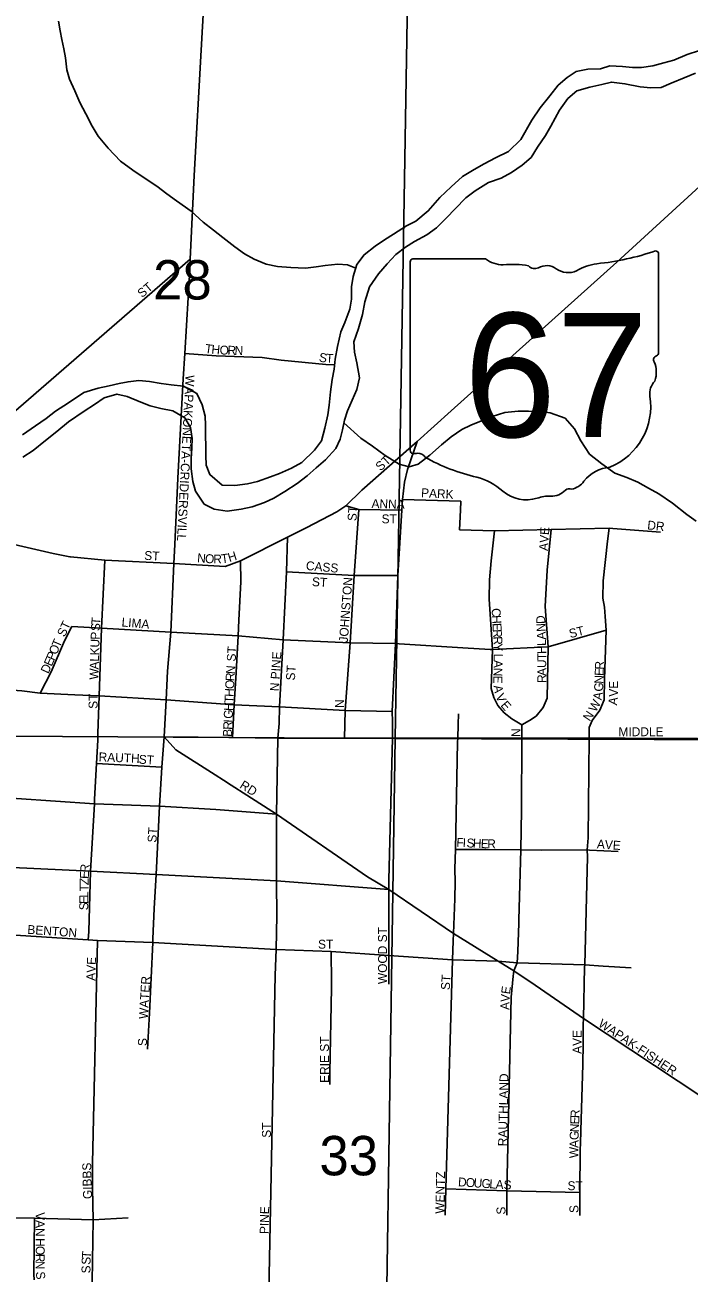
# Model space of a CAD drawing. Extents: x -784 to 1375, y -225 to 440.
# Drawn here: x 105.2 to 133.1, y 334.5 to 387.1 of the extents above; entities that cross this region are included whole.
import ezdxf

# ---------------------------------------------------------------- set-up
doc = ezdxf.new("R2010")
doc.units = 0
for name, color, linetype in [('GM_X_City_Street', 7, 'Continuous'), ('GM_X_City_Street_Text', 7, 'Continuous'), ('GM_X_Major_River', 7, 'Continuous'), ('GM_X_Minor_River', 7, 'Continuous'), ('GM_X_Section', 7, 'Continuous'), ('GM_X_Section_Text', 7, 'Continuous'), ('GM_X_State_Location', 7, 'Continuous'), ('GM_X_State_Route', 7, 'Continuous'), ('GM_X_State_Shield', 7, 'Continuous')]:
    doc.layers.add(name, color=color, linetype=linetype)

msp = doc.modelspace()

# ---------------------------------------------------------------- linework, layer by layer
at = {"layer": 'GM_X_City_Street'}
for points in [[(112.107, 376.784), (112.133, 377.221), (112.296, 380.735), (112.591, 386.006), (112.762, 389.014)], [(107.019, 372.788), (112.133, 377.221)], [(111.475, 365.212), (111.602, 368.004), (111.831, 372.18), (111.896, 373.25), (112.107, 376.784)], [(111.896, 373.25), (113.22, 373.152), (115.156, 373.078), (115.949, 372.972), (117.836, 372.788), (118.217, 372.764)], [(91.136, 368.057), (92.218, 368.088), (95.074, 368.197), (97.931, 368.286), (100.615, 368.4), (101.44, 368.441), (103.41, 369.658), (107.019, 372.788)], [(111.438, 364.408), (111.438, 364.408), (113.596, 364.282), (114.241, 364.525), (116.222, 365.515), (117.027, 365.93), (118.298, 366.578), (118.675, 366.84), (119.346, 367.498), (121.677, 369.543)], [(118.643, 358.22), (118.86, 361.075), (119.022, 363.909), (119.215, 366.68)], [(118.675, 366.84), (119.215, 366.68), (121.032, 366.649)], [(121.064, 367.096), (123.511, 367.026), (123.494, 366.648)], [(123.494, 366.648), (123.46, 365.831), (124.927, 365.786), (127.311, 365.838), (129.746, 365.895), (129.903, 365.882)], [(126.072, 357.619), (125.651, 357.865), (125.338, 358.13), (125.066, 358.431), (124.9, 358.772), (124.792, 359.143), (124.839, 360.787), (124.705, 362.905), (124.724, 363.723), (124.795, 364.522), (124.927, 365.786)], [(126.085, 357.057), (126.072, 357.619), (126.401, 357.808), (126.679, 357.983), (126.982, 358.347), (127.142, 358.737), (127.187, 360.905), (127.063, 362.593), (127.139, 364.125), (127.311, 365.838)], [(128.918, 357.068), (128.918, 357.501), (129.033, 357.801), (129.356, 358.242), (129.541, 358.676), (129.56, 359.545), (129.626, 361.602), (129.584, 362.184), (129.556, 362.578), (129.483, 362.944), (129.503, 363.685), (129.68, 365.342), (129.746, 365.895)], [(129.903, 365.882), (131.915, 365.724)], [(103.944, 365.378), (103.973, 365.372), (106.368, 364.833), (107.061, 364.692)], [(111.111, 358.673), (111.169, 359.874), (111.309, 361.516), (111.438, 364.408), (111.475, 365.212)], [(115.883, 358.373), (116.044, 361.202), (116.184, 364.065), (116.222, 365.515)], [(107.061, 364.692), (107.087, 364.686), (108.542, 364.551), (111.438, 364.408)], [(108.294, 358.836), (108.396, 361.682), (108.542, 364.551)], [(114.06, 359.824), (114.152, 361.369), (114.171, 362.027), (114.254, 363.643), (114.241, 364.525)], [(116.184, 364.065), (119.022, 363.909), (120.859, 363.897)], [(105.812, 358.954), (106.278, 359.844), (106.842, 361.152), (107.144, 361.757)], [(107.144, 361.757), (108.396, 361.682), (111.309, 361.516), (114.152, 361.369), (116.044, 361.202), (118.86, 361.075), (120.77, 361.037), (120.92, 361.028)], [(124.745, 360.793), (124.839, 360.787), (127.187, 360.905), (129.626, 361.602)], [(120.92, 361.028), (123.597, 360.863)], [(123.597, 360.863), (124.745, 360.793)], [(113.903, 357.083), (113.98, 358.462), (114.06, 359.824)], [(99.332, 359.444), (102.266, 359.248), (105.044, 359.044), (105.812, 358.954), (107.272, 358.878), (108.266, 358.837)], [(108.245, 357.255), (108.294, 358.836)], [(108.266, 358.837), (108.294, 358.836), (111.111, 358.673)], [(111.035, 357.115), (111.111, 358.673)], [(111.111, 358.673), (113.98, 358.462), (115.883, 358.373), (118.643, 358.22), (120.63, 358.181)], [(115.758, 353.703), (115.757, 353.865), (115.813, 357.063), (115.864, 357.67), (115.883, 358.373)], [(118.617, 357.063), (118.643, 358.22)], [(123.379, 356.885), (123.383, 357.063), (123.402, 357.632), (123.415, 358.079)], [(108.106, 354.49), (108.186, 355.987), (108.237, 356.98), (108.245, 357.255)], [(110.561, 348.607), (110.607, 349.893), (110.696, 351.324), (110.837, 354.198), (110.932, 355.834), (111.035, 357.115)], [(111.035, 357.115), (113.903, 357.083), (115.813, 357.063), (118.617, 357.063), (120.642, 357.063), (121.997, 357.057), (123.383, 357.063), (125.938, 357.057)], [(120.48, 350.682), (119.591, 351.217), (115.757, 353.865), (114.506, 354.664), (113.845, 355.086), (113.527, 355.289), (113.183, 355.509), (111.53, 356.565), (111.035, 357.115)], [(123.194, 348.525), (123.209, 348.835), (123.254, 350.292), (123.268, 351.013), (123.259, 351.561), (123.287, 352.374), (123.379, 356.885)], [(125.938, 357.057), (126.085, 357.057), (128.918, 357.068), (130.422, 357.063), (133.463, 357.044), (138.325, 357.009), (140.841, 356.958)], [(125.951, 349.415), (126.04, 352.355), (126.063, 354.029), (126.085, 357.057)], [(128.72, 347.422), (128.722, 347.515), (128.84, 352.068), (128.829, 352.355), (128.863, 352.862), (128.918, 357.068)], [(80.071, 355.87), (83.086, 355.68), (86.015, 355.53), (88.849, 355.346), (91.692, 355.228), (94.544, 355.08), (96.031, 354.974), (97.444, 354.917), (98.204, 354.868), (99.079, 354.811), (101.947, 354.664), (104.821, 354.525), (108.096, 354.301), (110.837, 354.198), (113.207, 354.051), (115.757, 353.865)], [(108.186, 355.987), (110.932, 355.834)], [(107.839, 348.564), (107.859, 348.922), (107.93, 351.458), (108.096, 354.301), (108.106, 354.49)], [(115.762, 350.978), (115.762, 351.055), (115.758, 353.703)], [(123.287, 352.374), (124.565, 352.368), (126.04, 352.355), (126.896, 352.349), (128.829, 352.355), (128.925, 352.351)], [(128.925, 352.351), (130.132, 352.295)], [(115.42, 333.071), (115.698, 347.082), (115.743, 348.168), (115.768, 349.599), (115.762, 350.978)], [(120.479, 347.901), (120.479, 347.915), (120.479, 347.964), (120.48, 350.473), (120.48, 350.682)], [(120.48, 350.682), (123.209, 348.835), (125.081, 347.668), (125.739, 347.264), (126.389, 346.827), (126.452, 346.784)], [(125.717, 347.035), (125.739, 347.264), (125.889, 347.601), (125.905, 348.081), (125.947, 349.276), (125.951, 349.415)], [(98.761, 349.05), (101.574, 348.935), (103.26, 348.845), (104.551, 348.781), (107.839, 348.564), (108.231, 348.541), (110.555, 348.456), (115.743, 348.168), (118.054, 348.079), (120.479, 347.915), (123.155, 347.733), (125.081, 347.668), (125.889, 347.601), (128.722, 347.515), (129.501, 347.466)], [(108.016, 339.136), (108.016, 339.167), (108.231, 348.541)], [(110.338, 343.965), (110.421, 345.479), (110.555, 348.456), (110.561, 348.607)], [(122.849, 336.983), (122.881, 338.086), (123.155, 347.733), (123.194, 348.525)], [(118.07, 346.788), (118.054, 348.079)], [(120.479, 346.709), (120.479, 347.127), (120.479, 347.901)], [(128.665, 345.01), (128.669, 345.259), (128.72, 347.422)], [(129.501, 347.466), (130.683, 347.392)], [(117.996, 342.483), (117.996, 342.986), (118.073, 346.549), (118.07, 346.788)], [(125.445, 336.983), (125.454, 338.009), (125.633, 346.153), (125.717, 347.035)], [(126.452, 346.784), (128.669, 345.259), (142.616, 336.025)], [(128.513, 336.971), (128.517, 337.368), (128.522, 337.941), (128.539, 339.753), (128.541, 339.994), (128.558, 340.547), (128.641, 343.328), (128.643, 343.407), (128.653, 344.122), (128.664, 344.917), (128.665, 345.01)], [(108.042, 336.784), (108.016, 338.12), (108.016, 339.136)], [(122.881, 338.086), (125.454, 338.009), (128.522, 337.941)], [(97.987, 336.937), (100.836, 336.893), (103.129, 336.893), (105.576, 336.855), (108.042, 336.784), (109.511, 336.874)], [(105.57, 334.261), (105.55, 334.504), (105.576, 336.855)], [(108.016, 335.047), (108.042, 336.784)], [(107.991, 333.309), (108.016, 335.047)]]:
    msp.add_lwpolyline(points, dxfattribs=at)
at = {"layer": 'GM_X_Major_River'}
for points in [[(133.557, 386), (133.029, 385.827), (132.47, 385.594), (132.048, 385.48), (131.596, 385.351), (131.114, 385.282), (130.739, 385.287), (130.319, 385.323), (129.779, 385.36), (129.386, 385.231), (128.86, 385.208), (128.363, 385.109), (127.984, 384.859), (127.604, 384.534), (127.253, 384.088), (126.856, 383.583), (126.503, 383.062), (126.042, 382.257), (125.524, 381.754), (124.965, 381.476), (124.496, 381.227), (124.072, 380.993), (123.588, 380.699), (123.101, 380.255), (122.629, 379.811), (122.141, 379.247), (121.625, 378.818), (121.231, 378.613)], [(121.189, 377.728), (121.568, 377.963), (122.083, 378.241), (122.492, 378.536), (122.903, 378.951), (123.269, 379.336), (123.726, 379.796), (124.12, 380.091), (124.681, 380.444), (125.209, 380.632), (125.648, 380.866), (126.087, 381.175), (126.467, 381.501), (126.743, 381.933), (127.08, 382.423), (127.296, 382.811), (127.665, 383.482), (128.018, 383.973), (128.397, 384.298), (128.94, 384.456), (129.437, 384.569), (129.844, 384.669), (130.414, 384.601), (131.058, 384.472), (131.508, 384.421), (131.944, 384.445), (132.367, 384.619), (132.911, 384.852), (133.379, 385.041)], [(121.231, 378.613), (120.686, 378.275), (120.307, 378.025), (119.913, 377.76), (119.443, 377.406), (119.137, 376.99), (118.98, 376.481), (118.914, 376.046), (118.907, 375.536), (118.841, 375.116), (118.638, 374.548), (118.468, 374.16), (118.325, 373.546), (118.227, 373.007), (118.177, 372.587), (118.096, 372.152), (118.029, 371.628), (117.976, 371.073), (117.911, 370.668), (117.798, 370.099), (117.656, 369.575), (117.35, 369.174), (116.817, 368.655), (116.394, 368.421), (115.88, 368.202), (115.502, 368.057), (114.959, 367.854), (114.537, 367.755), (114.01, 367.687), (113.47, 367.709), (112.95, 368.152), (112.805, 368.544), (112.781, 368.95), (112.786, 369.371), (112.776, 369.747), (112.768, 370.227), (112.758, 370.603), (112.629, 371.085), (112.41, 371.569), (111.843, 371.877), (111.333, 371.929), (110.913, 371.98), (110.419, 372.062), (109.969, 372.113), (109.517, 372.059), (109.141, 371.989), (108.719, 371.89), (108.252, 371.791), (107.649, 371.604), (107.012, 371.177), (106.467, 370.824), (106.072, 370.514), (105.617, 370.205), (105.071, 369.822)], [(105.089, 368.89), (105.528, 369.17), (106.044, 369.583), (106.515, 369.967), (107.001, 370.366), (107.668, 370.823), (108.108, 371.102), (108.502, 371.382), (109.045, 371.54), (109.479, 371.444), (110.047, 371.196), (110.45, 371.04), (110.899, 370.929), (111.394, 370.832), (111.901, 370.54), (112.135, 370.131), (112.204, 369.664), (112.199, 369.274), (112.163, 368.809), (112.172, 368.388), (112.24, 367.861), (112.355, 367.454), (112.708, 366.909), (113.141, 366.692), (113.681, 366.61), (114.268, 366.692), (114.734, 366.791), (115.248, 366.979), (115.641, 367.154), (116.11, 367.433), (116.625, 367.771), (117.05, 368.096), (117.43, 368.436), (117.825, 368.776), (118.252, 369.251), (118.438, 369.639), (118.533, 370.029), (118.614, 370.448), (118.739, 370.837), (119.142, 371.733), (119.253, 372.227), (119.142, 372.859), (119.042, 373.296), (119.018, 373.732), (119.206, 374.3), (119.379, 374.884), (119.476, 375.423), (119.665, 376.051), (120.048, 376.602), (120.414, 377.017), (120.78, 377.418), (121.189, 377.728)]]:
    msp.add_lwpolyline(points, dxfattribs=at)
at = {"layer": 'GM_X_Minor_River'}
for points in [[(119.089, 376.835), (118.746, 376.98), (118.341, 377.001), (117.799, 376.948), (117.423, 376.893), (116.972, 376.839), (116.356, 376.862), (115.801, 376.915), (115.322, 377.012), (114.814, 377.214), (114.411, 377.445), (114.01, 377.735), (113.504, 378.133), (113.103, 378.439), (112.672, 378.775), (112.167, 379.232), (111.557, 379.676), (111.14, 379.967), (110.724, 380.288), (110.143, 380.672), (109.712, 380.963), (109.191, 381.346), (108.673, 381.893), (108.259, 382.395), (108.009, 382.818), (107.731, 383.333), (107.482, 383.817), (107.278, 384.3), (107.044, 384.799), (106.944, 385.191), (106.876, 385.687), (106.806, 386.064), (106.721, 386.455), (106.651, 386.832), (106.581, 387.238)], [(133.413, 366.191), (133.026, 366.467), (132.416, 366.941), (131.836, 367.339), (131.403, 367.585), (130.956, 367.832), (130.493, 368.033), (129.985, 368.205), (129.449, 368.603), (128.929, 369.016), (128.561, 369.577), (128.297, 370.076), (127.898, 370.532), (127.27, 370.751), (126.865, 370.801), (126.354, 370.823), (125.919, 370.814), (125.362, 370.762), (124.834, 370.589), (124.381, 370.415), (123.928, 370.225), (123.55, 370.05), (123.111, 369.741), (122.7, 369.401), (122.214, 368.972), (121.713, 368.588), (121.336, 368.473), (120.917, 368.584), (120.336, 368.953), (119.801, 369.35), (119.31, 369.688), (118.591, 370.329)]]:
    msp.add_lwpolyline(points, dxfattribs=at)
at = {"layer": 'GM_X_Section'}
for points in [[(121.281, 389.014), (120.755, 357.05), (81.068, 357.283), (81.709, 397.114), (86.63, 397.087)], [(133.637, 396.836), (161.159, 396.705), (160.697, 356.887), (120.755, 357.05), (121.281, 389.014)]]:
    msp.add_lwpolyline(points, dxfattribs=at)
for points in [[(81.068, 357.283), (120.755, 357.05), (120.146, 317.31), (119.981, 317.313), (80.486, 317.362)], [(120.755, 357.05), (160.697, 356.887), (159.863, 317.136), (120.146, 317.31)]]:
    msp.add_lwpolyline(points, close=True, dxfattribs=at)
at = {"layer": 'GM_X_State_Route'}
for points in [[(123.112, 370.833), (130.071, 377.093), (137.891, 384.241), (137.973, 384.32)], [(121.406, 368.77), (121.677, 369.543), (123.112, 370.833)], [(120.634, 357.765), (120.63, 358.181), (120.77, 361.037), (120.859, 363.897), (121.032, 366.649), (121.064, 367.096), (121.147, 367.837), (121.262, 368.361), (121.406, 368.77)], [(120.49, 351.099), (120.642, 357.063), (120.634, 357.765)], [(98.919, 351.93), (101.765, 351.752), (104.653, 351.611), (107.93, 351.458), (110.696, 351.324), (115.762, 351.055), (120.48, 350.682), (120.49, 351.099)]]:
    msp.add_lwpolyline(points, dxfattribs=at)
at = {"layer": 'GM_X_State_Shield'}
for p, q in [((124.548, 377.235), (121.49, 377.235)), ((131.828, 373.286), (131.828, 377.432)), ((121.387, 377.099), (121.387, 369.174)), ((131.827, 373.287), (131.828, 373.286))]:
    msp.add_line(p, q, dxfattribs=at)
for centre, radius, start, end in [((121.507, 377.116), 0.121, 98.1301, 188.1301), ((125.276, 378.155), 1.173, 231.6195, 271.1119), ((128.109, 388.04), 11.073, 275.8445, 288.9065), ((131.712, 377.449), 0.116, 351.8621, 97.738), ((125.665, 372.786), 4.212, 80.4867, 94.9883), ((126.621, 377.157), 0.338, 219.7921, 297.1024), ((127.118, 376.241), 0.704, 54.4667, 119.1411), ((128.026, 377.497), 0.847, 233.8562, 294.8282), ((129.521, 374.815), 2.228, 97.3462, 120.7689), ((131.801, 372.982), 0.18, 107.944, 210.337), ((131.704, 373.27), 0.124, 289.6038, 7.7341), ((130.657, 372.458), 1.08, 340.033, 23.6496), ((132.245, 371.551), 0.786, 136.8065, 186.9296), ((128.729, 371.024), 2.77, 292.3089, 8.9858), ((121.508, 369.157), 0.122, 171.9584, 258.3066), ((121.526, 369.968), 0.931, 267.339, 280.6039), ((121.717, 368.717), 0.336, 29.7484, 93.2717), ((125.956, 375.837), 7.996, 240.4129, 257.1985), ((129.897, 366.95), 1.517, 94.4031, 142.5768), ((123.572, 365.614), 2.502, 47.1842, 75.836), ((127.975, 368.406), 0.895, 282.8732, 323.2771), ((126.278, 368.678), 1.588, 230.7004, 286.2918), ((127.196, 365.938), 1.304, 85.6951, 111.2099), ((127.311, 368.084), 0.846, 268.777, 315.5493), ((128.077, 367.317), 0.238, 65.7517, 132.6484)]:
    msp.add_arc(centre, radius, start, end, dxfattribs=at)

# ---------------------------------------------------------------- texts
at = {"layer": 'GM_X_City_Street_Text'}
for s, rotation, p in [('ST', 39.7984, (110.102, 375.572)), ('T', 352.5462, (112.731, 373.278)), ('H', 354.5863, (113.007, 373.242)), ('O', 358.1913, (113.361, 373.209)), ('R', 358.3428, (113.692, 373.199)), ('N', 358.3602, (113.989, 373.19)), ('S', 350.2009, (117.523, 372.914)), ('T', 357.0375, (117.831, 372.863)), ('WAPAKONETA-CRIDERSVILL', 267.0333, (111.934, 372.346)), ('ST', 42.5022, (120.132, 368.277)), ('PARK', 356.9075, (121.833, 367.202)), ('ST', 86.1879, (119.119, 366.184)), ('ANNA', 358.5321, (119.752, 366.745)), ('ST', 0, (120.179, 366.099)), ('DR', 353.6625, (131.341, 365.848)), ('AVE', 85.9166, (127.171, 364.93)), ('ST', 356.4126, (110.185, 364.566)), ('N', 355.4883, (112.41, 364.464)), ('O', 355.4883, (112.739, 364.438)), ('R', 359.7817, (113.098, 364.411)), ('T', 8.3685, (113.456, 364.414)), ('H', 16.9553, (113.777, 364.466)), ('CASS', 355.0974, (116.984, 364.137)), ('ST', 356.4126, (117.239, 363.461)), ('JOHNSTON', 85.8146, (118.756, 361.069)), ('C', 273.2809, (124.804, 362.52)), ('ST', 64.9879, (106.849, 361.292)), ('T', 85.7061, (108.338, 361.819)), ('LIMA', 355.1036, (109.229, 361.761)), ('H', 273.2587, (124.821, 362.224)), ('D', 92.2959, (127.066, 361.872)), ('P', 88.2345, (108.313, 361.197)), ('S', 86.9657, (108.324, 361.558)), ('E', 273.2798, (124.84, 361.894)), ('R', 273.2809, (124.855, 361.631)), ('N', 92.2923, (127.079, 361.542)), ('A', 92.2923, (127.092, 361.212)), ('ST', 14.0427, (128.115, 361.264)), ('O', 66.9851, (106.506, 360.541)), ('T', 66.9556, (106.635, 360.845)), ('K', 88.2363, (108.293, 360.537)), ('U', 88.251, (108.303, 360.867)), ('ST', 86.4118, (114.037, 360.276)), ('R', 273.2809, (124.872, 361.334)), ('Y', 271.8582, (124.889, 361.04)), ('L', 91.9522, (127.101, 360.946)), ('H', 90.4995, (127.104, 360.605)), ('E', 66.8167, (106.299, 360.055)), ('P', 66.9624, (106.403, 360.298)), ('L', 88.251, (108.285, 360.274)), ('N PINE', 86.0966, (115.852, 359.023)), ('A', 269.2045, (124.895, 360.351)), ('L', 269.1257, (124.899, 360.616)), ('T', 90.0206, (127.104, 360.338)), ('U', 90.0154, (127.104, 360.008)), ('D', 65.5759, (106.159, 359.746)), ('W', 88.251, (108.262, 359.515)), ('A', 88.2476, (108.275, 359.944)), ('N', 85.1855, (114.002, 359.741)), ('ST', 86.4254, (116.529, 359.477)), ('N', 269.2045, (124.89, 360.021)), ('A', 90, (127.104, 359.678)), ('E', 87.8945, (129.517, 359.673)), ('R', 87.8627, (129.527, 359.937)), ('O', 87.2009, (113.97, 359.118)), ('R', 86.9872, (113.986, 359.447)), ('E', 269.216, (124.886, 359.692)), ('R', 90.0243, (127.105, 359.381)), ('G', 87.6059, (129.491, 359.012)), ('N', 87.8649, (129.505, 359.343)), ('E', 89.9073, (130.126, 359.135)), ('ST', 90, (108.229, 358.292)), ('T', 87.1853, (113.941, 358.525)), ('H', 87.2006, (113.954, 358.789)), ('A', 278.3651, (124.885, 359.263)), ('V', 294.2941, (124.965, 358.828)), ('A', 81.353, (129.437, 358.641)), ('A', 83.0105, (130.078, 358.429)), ('V', 89.2385, (130.121, 358.801)), ('G', 87.2006, (113.909, 357.866)), ('H', 87.2006, (113.925, 358.195)), ('N', 90, (118.591, 358.325)), ('E', 310.8055, (125.164, 358.428)), ('W', 62.0266, (129.193, 358.131)), ('R', 87.1813, (113.886, 357.404)), ('I', 87.2045, (113.901, 357.701)), ('N', 56.1826, (128.933, 357.739)), ('B', 87.2055, (113.872, 357.107)), ('N', 90, (126.016, 357.104)), ('MIDDLE', 0, (130.145, 357.141)), ('RAUTH', 357.6108, (108.269, 356.086)), ('ST', 356.4262, (109.954, 355.987)), ('RD', 327.9873, (114.178, 354.986)), ('ST', 86.4254, (110.704, 352.653)), ('F', 357.0202, (123.318, 352.488)), ('I', 357.0298, (123.582, 352.475)), ('S', 356.993, (123.746, 352.466)), ('H', 357.0316, (124.01, 352.452)), ('E', 357.8199, (124.345, 352.435)), ('R', 359.6258, (124.622, 352.425)), ('AVE', 355.9088, (129.226, 352.423)), ('E', 88.4422, (107.86, 351.132)), ('R', 85.1859, (107.867, 351.39)), ('T', 88.8253, (107.849, 350.604)), ('Z', 88.798, (107.854, 350.868)), ('E', 88.8253, (107.838, 350.076)), ('L', 88.8253, (107.844, 350.34)), ('S', 88.8253, (107.833, 349.812)), ('BENTON', 355.9127, (105.268, 348.825)), ('WOOD ST', 90, (120.406, 346.709)), ('ST', 0, (117.506, 348.199)), ('AVE', 88.0261, (108.13, 346.843)), ('WATER', 86.4942, (110.341, 345.228)), ('ST', 86.4254, (123.046, 346.449)), ('V', 86.6759, (125.555, 345.944)), ('E', 81.7192, (125.573, 346.265)), ('A', 89.8032, (125.554, 345.62)), ('WAPAK-FISHER', 326.465, (129.26, 344.953)), ('AVE', 90, (128.59, 343.772)), ('S', 90, (110.308, 344.102)), ('ERIE ST', 90, (117.964, 342.551)), ('RAUTHLAND', 88.8049, (125.455, 339.88)), ('E', 87.8448, (128.487, 340.798)), ('R', 87.8385, (128.497, 341.062)), ('ST', 90, (115.522, 340.241)), ('G', 87.8797, (128.463, 340.138)), ('N', 87.836, (128.475, 340.468)), ('W', 89.9496, (128.458, 339.383)), ('A', 89.1694, (128.458, 339.811)), ('GIBBS', 91.3964, (107.998, 337.665)), ('WENTZ', 88.8315, (122.815, 337.041)), ('D', 356.4128, (123.385, 338.2)), ('O', 356.4123, (123.714, 338.179)), ('U', 356.3909, (124.043, 338.158)), ('G', 356.4123, (124.373, 338.138)), ('L', 356.418, (124.702, 338.117)), ('A', 356.3909, (124.966, 338.1)), ('S', 357.629, (125.304, 338.079)), ('ST', 0, (128, 338.035)), ('PINE', 88.6036, (115.423, 336.184)), ('S', 90, (125.389, 337.007)), ('S', 90, (128.458, 337.073)), ('V', 270.0219, (105.631, 337.106)), ('A', 270.0379, (105.631, 336.776)), ('N', 270.0219, (105.631, 336.446)), ('O', 270.0219, (105.632, 335.687)), ('H', 270.0379, (105.631, 336.017)), ('R', 270.0178, (105.632, 335.357)), ('S', 88.1964, (107.932, 334.892)), ('T', 86.0078, (107.941, 335.152)), ('N', 270.0379, (105.632, 335.06)), ('S', 89.9727, (107.932, 334.532)), ('S', 274.8192, (105.634, 334.597))]:
    msp.add_text(s, height=0.375, rotation=rotation, dxfattribs=at).set_placement(p)
at = {"layer": 'GM_X_Section_Text'}
for s, p in [('28', (110.568, 375.52)), ('33', (117.564, 338.66))]:
    msp.add_text(s, height=1.6575, rotation=0, dxfattribs=at).set_placement(p)
at = {"layer": 'GM_X_State_Location'}
for s in ['s', 'r']:
    msp.add_text(s, height=0.0075, dxfattribs=at).set_placement((126.49, 372.61))
msp.add_text('67', height=0.0075, rotation=0, dxfattribs=at).set_placement((124.601, 372.064))
at = {"layer": 'GM_X_State_Shield'}
msp.add_text('67', height=5.2207, dxfattribs=at).set_placement((123.64, 369.733))

doc.saveas('drawing.dxf')
